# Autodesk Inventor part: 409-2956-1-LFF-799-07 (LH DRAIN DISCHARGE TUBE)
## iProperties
Created: 2010-11
Part Number: 409-2956-1-LFF-799-07 (LH DRAIN DISCHARGE TUBE)
Material: 3/4" OD TUBE - SS
Document SubType Name: Modeling
Designer: S. Boerckel
Engineer: Steve Boerckel
Density: 8.08 g/cm^3
Description: DRAIN TUBING
Length: 18.395 in
Author: S. Boerckel
Revision Number: 0
